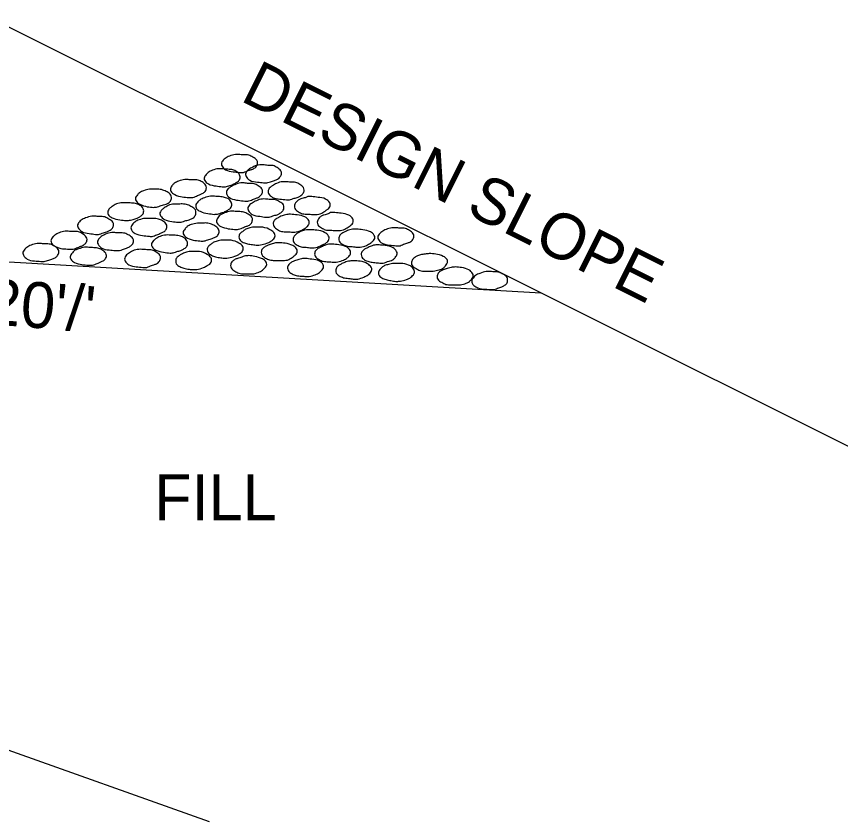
# Model space of a CAD drawing. Extents: x 438659 to 573674, y 10724 to 98600.
# Drawn here: x 516659 to 519895, y 68148 to 71311 of the extents above; entities that cross this region are included whole.
import ezdxf

# ---------------------------------------------------------------- set-up
doc = ezdxf.new("R2010")
doc.units = 0
doc.layers.add('T_Vehicle Path Rt', color=7, linetype='Continuous')

msp = doc.modelspace()

# ---------------------------------------------------------------- linework, layer by layer
at = {"layer": 'T_Vehicle Path Rt'}
for p, q in [((520270.3, 69449), (516544.6, 71311.4)), ((514103.7, 70495.3), (518717.5, 70225)), ((512200.6, 70004), (517415.7, 68148.2))]:
    msp.add_line(p, q, dxfattribs=at)
for points in [[(517534.1, 70698.2), (517509.1, 70701.3), (517480, 70708.9), (517465.7, 70723.7), (517463.5, 70731.4), (517470.8, 70747), (517477.8, 70753.8), (517495, 70762.7), (517518.8, 70768.8), (517531.4, 70768.8), (517550.4, 70767.8), (517571, 70766.4), (517586.8, 70758.4), (517602.5, 70746.2), (517605, 70735.3), (517600.6, 70722.7), (517588.9, 70713), (517577.5, 70708.6), (517560.5, 70702.6), (517550.4, 70698.7), (517534.1, 70698.2)], [(517466.9, 70642.4), (517442.1, 70645.3), (517412, 70653.3), (517397.7, 70667.1), (517395.8, 70675.9), (517403.3, 70690.4), (517411.3, 70697.7), (517428.1, 70707.2), (517451.6, 70713), (517464.5, 70713), (517482.9, 70711), (517504.3, 70709.8), (517519.8, 70703.8), (517534.1, 70689.7), (517536.5, 70681.2), (517532.2, 70666.6), (517521, 70658.4), (517509.8, 70652.3), (517492.6, 70645.8), (517482.9, 70642.9), (517466.9, 70642.4)], [(517629.2, 70657.7), (517605, 70660.8), (517574.6, 70667.9), (517560.1, 70682.7), (517557.9, 70690.2), (517565.6, 70706.2), (517574.1, 70712.3), (517590.6, 70721.7), (517614.2, 70728.3), (517626.3, 70728.3), (517645.7, 70726.3), (517666.3, 70725.4), (517682.6, 70717.4), (517696.9, 70705), (517699.6, 70694.5), (517694.7, 70682.4), (517684.1, 70672), (517671.9, 70667.1), (517655.7, 70661.5), (517645.7, 70658.4), (517629.2, 70657.7)], [(517335.4, 70599.9), (517309.6, 70602.6), (517280, 70611.3), (517264.8, 70624.7), (517263.3, 70634.1), (517270.8, 70648.9), (517279.1, 70656.2), (517295.3, 70664.7), (517319.6, 70670.3), (517332.2, 70670.3), (517351.1, 70669.3), (517372.2, 70668.1), (517387.3, 70661.3), (517401.9, 70647.7), (517404.3, 70638.7), (517399.4, 70624.2), (517388, 70615.7), (517377.1, 70611.1), (517361.1, 70604), (517351.1, 70600.2), (517335.4, 70599.9)], [(517555.5, 70586.3), (517529.5, 70589), (517500.1, 70596.8), (517484.8, 70611.3), (517482.9, 70619.3), (517490.4, 70635.1), (517498.9, 70641.4), (517515.7, 70650.4), (517539.7, 70657.2), (517552.3, 70657.2), (517571, 70655.2), (517591.8, 70654.3), (517607.1, 70645.8), (517622.2, 70634.1), (517624.6, 70623.2), (517619.8, 70610.6), (517608.1, 70600.4), (517597.4, 70596.5), (517581.2, 70590.2), (517571, 70586.6), (517555.5, 70586.3)], [(517719.5, 70591.4), (517693, 70594.1), (517664.4, 70600.6), (517648.4, 70616.2), (517646.7, 70623.7), (517654.5, 70639.5), (517663.2, 70645.8), (517679.9, 70655.7), (517704, 70661.8), (517715.8, 70661.8), (517735, 70660.8), (517755.6, 70659.4), (517771.7, 70651.1), (517785.5, 70639), (517788.2, 70628.8), (517783.5, 70615.4), (517772.6, 70605.7), (517761.2, 70600.4), (517745, 70595.5), (517735, 70591.9), (517719.5, 70591.4)], [(517197.1, 70561.3), (517172.3, 70564), (517142.5, 70574.2), (517128.1, 70586.6), (517125.5, 70595.5), (517133.5, 70610.6), (517141.7, 70618.4), (517157.5, 70626.8), (517181, 70632.4), (517194.4, 70632.4), (517212.8, 70633.4), (517233.5, 70629.3), (517250.2, 70621.8), (517264.8, 70609.4), (517266.9, 70599.9), (517263.3, 70585.8), (517251.4, 70576.1), (517240.7, 70572.5), (517222.8, 70566.7), (517212.8, 70563), (517197.1, 70561.3)], [(517435.3, 70533.9), (517409.9, 70537.1), (517379.8, 70545.8), (517364, 70558.9), (517362.3, 70568.1), (517370.6, 70582.7), (517378.6, 70590.2), (517396.8, 70599.4), (517420.1, 70605), (517431.9, 70605), (517450.9, 70604), (517471.3, 70601.6), (517488, 70595.8), (517501.6, 70581.5), (517504.3, 70573.5), (517499.4, 70558.4), (517488.5, 70550.7), (517477.3, 70544.6), (517461.8, 70539.3), (517451.6, 70535.9), (517435.3, 70533.9)], [(517639.2, 70522.5), (517613.9, 70526.1), (517584.3, 70533.2), (517569.8, 70548), (517567.3, 70555.8), (517574.9, 70572), (517583.6, 70577.6), (517600.6, 70587.5), (517624.1, 70594.1), (517636.5, 70594.1), (517654.9, 70592.1), (517676.1, 70590.9), (517691.6, 70583.2), (517706.9, 70570.8), (517709.1, 70560.4), (517704.7, 70547.7), (517692.8, 70538), (517682.1, 70532.5), (517665.1, 70527.6), (517654.9, 70523.5), (517639.2, 70522.5)], [(517818.2, 70604), (517842.8, 70600.6), (517872.6, 70594.1), (517888.6, 70579), (517890.6, 70571.8), (517883.5, 70555.5), (517874.5, 70549.7), (517857.1, 70538.8), (517833.5, 70533.2), (517821.2, 70533.2), (517803, 70534.9), (517781.4, 70536.3), (517765.6, 70543.6), (517751.8, 70556.5), (517749.8, 70566.7), (517754.4, 70579.5), (517764.4, 70589.5), (517775.5, 70595.1), (517792, 70599.4), (517802.5, 70603.6), (517818.2, 70604)], [(517089.8, 70509.4), (517064.1, 70512.1), (517034.7, 70520.1), (517018.9, 70533.4), (517017.2, 70542.4), (517024.3, 70557.2), (517034, 70564.5), (517051.2, 70574.9), (517074.8, 70579.5), (517086.6, 70579.5), (517105.1, 70578.6), (517126.2, 70576.4), (517142, 70570.3), (517156.5, 70556), (517158.2, 70547.7), (517153.6, 70533.2), (517142.5, 70524.7), (517132, 70518.9), (517116.2, 70513.8), (517106.1, 70511.1), (517089.8, 70509.4)], [(517293.6, 70502.9), (517268.6, 70505.8), (517239.8, 70513.8), (517224.5, 70528.1), (517221.8, 70535.4), (517229.8, 70552.1), (517238.8, 70558.9), (517253.8, 70568.6), (517278.1, 70574.2), (517291, 70574.2), (517309.6, 70574.7), (517330.8, 70571.3), (517346.8, 70563), (517361.6, 70551.1), (517363.5, 70541.4), (517359.4, 70527.6), (517348.2, 70517.4), (517336.6, 70512.6), (517319.6, 70507.9), (517309.6, 70504.6), (517293.6, 70502.9)], [(516969.2, 70455.3), (516944, 70458.2), (516915.1, 70466.2), (516901, 70480.8), (516898.3, 70488.8), (516905.6, 70504.6), (516912.7, 70511.1), (516929.6, 70519.6), (516953.9, 70526.6), (516966.3, 70526.6), (516984.7, 70525.2), (517005.8, 70523.5), (517021.6, 70515.5), (517037.4, 70503.3), (517039.6, 70492.9), (517035.2, 70479.8), (517023.3, 70470.3), (517012.9, 70465.7), (516995.4, 70459.4), (516984.7, 70455.8), (516969.2, 70455.3)], [(517179.6, 70447.5), (517153.6, 70450.7), (517124.7, 70458.4), (517110.2, 70472.5), (517108.2, 70481.3), (517115.8, 70496.3), (517122.8, 70503.8), (517140.3, 70512.3), (517163.8, 70517.9), (517176.2, 70517.9), (517195.4, 70517.2), (517216.2, 70515.5), (517231.8, 70508.7), (517247, 70495.1), (517249.2, 70486.4), (517244.4, 70471.6), (517233.5, 70463.5), (517221.8, 70458.2), (517205.1, 70451.7), (517195.4, 70447.8), (517179.6, 70447.5)], [(517514.9, 70474.9), (517490.2, 70477.6), (517460.8, 70486.4), (517446, 70499.9), (517444.3, 70508.7), (517451.6, 70524), (517458.6, 70530.8), (517476.1, 70539.3), (517499.6, 70545.8), (517512, 70545.8), (517530.9, 70544.6), (517551.8, 70542.9), (517567.8, 70534.9), (517583.4, 70522.5), (517585.1, 70512.6), (517580.9, 70499), (517569.8, 70490), (517558.4, 70485.9), (517541.4, 70478.8), (517530.9, 70475.4), (517514.9, 70474.9)], [(517735.3, 70534.4), (517761.2, 70531.7), (517790.8, 70524), (517806.4, 70509.6), (517808.1, 70501.2), (517800.8, 70486.6), (517792, 70479.3), (517774.6, 70469.9), (517751.3, 70464.3), (517738.4, 70464.3), (517720.2, 70465.7), (517699.1, 70466.7), (517683.6, 70473.7), (517669, 70487.3), (517666.8, 70496.3), (517671.2, 70510.1), (517683.1, 70518.9), (517693, 70524.7), (517710, 70530.8), (517720.2, 70533.4), (517735.3, 70534.4)], [(517908.5, 70540.9), (517934, 70538.3), (517963.6, 70530.8), (517979.4, 70516), (517981.3, 70508.4), (517973.5, 70492.4), (517965.3, 70486.4), (517947.6, 70475.7), (517924.8, 70470.3), (517911.7, 70470.3), (517892.7, 70471.6), (517871.1, 70473), (517856.3, 70481), (517841.8, 70493.1), (517839.8, 70503.8), (517844.7, 70516.7), (517855.1, 70526.6), (517866, 70531), (517883, 70536.3), (517892.3, 70540.5), (517908.5, 70540.9)], [(517384.4, 70428.8), (517359.4, 70431.5), (517330.3, 70440.5), (517315.2, 70453.6), (517312.8, 70462.1), (517320.6, 70477.1), (517329.3, 70485.9), (517344.6, 70493.6), (517368.9, 70499), (517381.2, 70499), (517399.7, 70499.9), (517420.8, 70496.3), (517437, 70489), (517452.1, 70475.7), (517454.3, 70467.4), (517449.9, 70452.6), (517438.5, 70444.1), (517427.1, 70438.8), (517410.3, 70433.9), (517399.7, 70430.1), (517384.4, 70428.8)], [(517602, 70483.7), (517626.3, 70483), (517657.4, 70472), (517671.4, 70458.4), (517673.9, 70449.7), (517665.9, 70434.9), (517657.9, 70427.9), (517641.4, 70420.4), (517616.8, 70413.8), (517604.5, 70412.8), (517585.5, 70414.8), (517565.6, 70417.9), (517549.4, 70423.3), (517534.6, 70435.9), (517532.4, 70444.9), (517536.8, 70458.9), (517548.7, 70467.9), (517559.1, 70475.4), (517575.3, 70480.8), (517585.8, 70483), (517602, 70483.7)], [(516864.9, 70397.3), (516839.4, 70399), (516811.2, 70407.5), (516795.7, 70421.3), (516793.8, 70430.1), (516801.5, 70445.3), (516809.5, 70452.4), (516826, 70461.6), (516849.3, 70467.4), (516861.9, 70467.4), (516881.6, 70466.5), (516902.7, 70465.2), (516917.5, 70457.5), (516932.8, 70444.6), (516935.5, 70434.9), (516930.6, 70421.1), (516919.9, 70412.3), (516907.6, 70407), (516890.6, 70400.2), (516881.6, 70397.3), (516864.9, 70397.3)], [(517047.6, 70391.7), (517022.1, 70394.1), (516993.7, 70401.4), (516978.9, 70416.2), (516976.5, 70424.2), (516984.2, 70440), (516991.5, 70446.3), (517008.5, 70455.8), (517032.8, 70462.1), (517044.2, 70462.1), (517063.6, 70460.9), (517084.2, 70459.4), (517100.5, 70451.7), (517115.8, 70438.8), (517118.2, 70429.1), (517113.3, 70415.5), (517101.9, 70406.3), (517090.8, 70400.9), (517074.5, 70395.6), (517063.6, 70392), (517047.6, 70391.7)], [(517262.3, 70381.5), (517236.4, 70384.7), (517206.3, 70393.4), (517191, 70406.5), (517188.3, 70415.5), (517196.6, 70430.5), (517205.1, 70437.6), (517222.3, 70447), (517245.8, 70452.6), (517258.4, 70452.6), (517276.9, 70451.9), (517298, 70449.7), (517314, 70443.2), (517328.1, 70429.3), (517330.8, 70420.4), (517325.7, 70406.3), (517314.3, 70397.3), (517303.6, 70392.2), (517287.8, 70387.4), (517277.6, 70383.5), (517262.3, 70381.5)], [(517812.9, 70473.5), (517838.4, 70471.6), (517868.5, 70463.1), (517884.5, 70448.3), (517886.4, 70440), (517878.2, 70424.5), (517869.4, 70418.4), (517852, 70410.4), (517828, 70402.2), (517815.3, 70402.2), (517796.6, 70404.3), (517776.3, 70406.5), (517761, 70413.3), (517746.9, 70425.7), (517744.5, 70435.4), (517749.3, 70448.7), (517759.3, 70458.2), (517769.7, 70464.3), (517786.2, 70470.3), (517796.9, 70472.5), (517812.9, 70473.5)], [(517993.9, 70475.7), (518018.9, 70473), (518048.3, 70465.5), (518063.8, 70451.4), (518066, 70443.2), (518057.3, 70427.4), (518049, 70421.1), (518032.5, 70411.9), (518008.5, 70405.1), (517996.1, 70405.1), (517977.4, 70407), (517956.8, 70408.5), (517940.8, 70415.5), (517926.2, 70428.8), (517924.8, 70438.1), (517928.2, 70451.7), (517939.8, 70460.9), (517950.5, 70466.2), (517967.2, 70473), (517978.4, 70475.4), (517993.9, 70475.7)], [(518148.7, 70410.4), (518123.7, 70413.3), (518094.4, 70421.1), (518079.8, 70435.2), (518077.4, 70443.6), (518085.6, 70458.9), (518092.9, 70465.7), (518109.9, 70474.5), (518133, 70481), (518146.3, 70481), (518165, 70479.8), (518185.9, 70478.1), (518201.4, 70470.3), (518216.7, 70457.7), (518218.9, 70447.5), (518214.5, 70434.4), (518203.6, 70425), (518191.9, 70420.8), (518174.5, 70414.3), (518165, 70410.6), (518148.7, 70410.4)], [(516754.2, 70348.8), (516729.2, 70351), (516700.3, 70358.2), (516686, 70373.3), (516683.4, 70381), (516691.6, 70397.3), (516698.6, 70403.6), (516715.6, 70413.3), (516739.7, 70419.1), (516751.5, 70419.1), (516771, 70417.9), (516792.1, 70416.2), (516808.3, 70408.7), (516822.4, 70396.3), (516825.1, 70386.1), (516820.2, 70372.8), (516810, 70363.3), (516797.2, 70357.7), (516780.9, 70352.4), (516771, 70349.3), (516754.2, 70348.8)], [(517477.1, 70432.5), (517502.1, 70431.8), (517532.2, 70421.3), (517547, 70407.5), (517549.1, 70398.5), (517541.4, 70383.5), (517532.4, 70376.7), (517516.1, 70369.2), (517491.1, 70362.4), (517479.3, 70361.1), (517460.8, 70363.3), (517440.7, 70367), (517424.4, 70373.3), (517409.9, 70384.7), (517407.7, 70394.6), (517412, 70408), (517423.4, 70417), (517433.9, 70424.2), (517450.9, 70429.3), (517461.3, 70431.8), (517477.1, 70432.5)], [(517688.4, 70422.3), (517713.4, 70420.4), (517743.5, 70411.4), (517758.8, 70397.8), (517761.2, 70389.8), (517753.5, 70374.2), (517745, 70367.5), (517727.7, 70356.3), (517704.7, 70352.4), (517691.6, 70352.4), (517672.4, 70352.9), (517652, 70354.8), (517636.5, 70362.1), (517622.2, 70375.5), (517619.8, 70384.7), (517624.6, 70398.3), (517635.8, 70407.5), (517646.7, 70412.8), (517662.7, 70417.9), (517672.2, 70421.1), (517688.4, 70422.3)], [(516941.5, 70334), (516915.6, 70336.4), (516886.2, 70344.6), (516871.7, 70358.2), (516869.2, 70367.5), (516878.2, 70382.5), (516884.3, 70389.8), (516902.7, 70398.3), (516925.8, 70404.3), (516937.9, 70404.3), (516957.1, 70403.1), (516977.7, 70401.4), (516993.7, 70394.6), (517009, 70381), (517011.7, 70372.1), (517006.3, 70357.5), (516995.4, 70349.5), (516984.2, 70344.2), (516966.8, 70337.4), (516957.1, 70334.5), (516941.5, 70334)], [(517154.1, 70325.2), (517128.9, 70328.1), (517100, 70335.9), (517085.2, 70350.5), (517083.2, 70357.7), (517090.8, 70374.2), (517098.3, 70380.3), (517115, 70390.3), (517138.8, 70396.3), (517151.2, 70396.3), (517170.6, 70395.1), (517191, 70393.4), (517206.8, 70385.7), (517221.8, 70373.3), (517224.5, 70362.8), (517220.3, 70349.7), (517208.5, 70339.8), (517197.5, 70335.7), (517180.1, 70329.6), (517170.6, 70325.5), (517154.1, 70325.2)], [(517353.3, 70387.8), (517377.3, 70387.4), (517407.7, 70376.7), (517422.5, 70362.8), (517424.9, 70354.6), (517417.4, 70338.6), (517407.9, 70332.8), (517392.4, 70324.5), (517367.4, 70317.7), (517355, 70316.7), (517336.6, 70318.2), (517316.2, 70322.3), (517300.4, 70328.6), (517285.9, 70339.8), (517283.7, 70350.2), (517287.8, 70363.3), (517299.2, 70372.8), (517309.9, 70379.3), (517326.4, 70384.7), (517337.1, 70387.4), (517353.3, 70387.8)], [(517899, 70416.5), (517924.8, 70414.3), (517954.1, 70405.8), (517968.7, 70392), (517970.9, 70383.2), (517963.6, 70368.4), (517954.6, 70360.7), (517938.1, 70352.4), (517914.3, 70346.1), (517902.4, 70346.1), (517883.5, 70347.8), (517862.7, 70349.3), (517846.9, 70356.3), (517831.1, 70369.2), (517829.4, 70377.9), (517834, 70392.4), (517845.9, 70400.9), (517856.6, 70406.3), (517872.6, 70413.3), (517883.5, 70416.2), (517899, 70416.5)], [(518082.3, 70413.6), (518106.8, 70411.9), (518137.6, 70402.2), (518151.4, 70388.3), (518153.6, 70379.3), (518146.3, 70364.3), (518139, 70357), (518121.6, 70350.2), (518098, 70342.5), (518085.6, 70342.5), (518066, 70344.2), (518046.1, 70347.3), (518029.8, 70353.1), (518015, 70365.8), (518012.1, 70375.9), (518017.5, 70389.3), (518028.1, 70398.3), (518040.3, 70404.1), (518055.8, 70410.6), (518066, 70413.3), (518082.3, 70413.6)], [(517569.8, 70371.8), (517594.5, 70368.9), (517624.1, 70358.7), (517638.9, 70346.3), (517641.4, 70337.4), (517633.1, 70322.8), (517624.6, 70314.8), (517608.1, 70305.6), (517584.3, 70300), (517572, 70300), (517553.3, 70299.8), (517532.4, 70302.9), (517516.1, 70310.7), (517501.6, 70323.5), (517499.4, 70332.3), (517504.3, 70346.8), (517514.9, 70355.8), (517526.6, 70360.7), (517543.6, 70366.2), (517553.3, 70369.6), (517569.8, 70371.8)], [(517793.3, 70360.7), (517818.7, 70357.5), (517848.1, 70350.5), (517862.7, 70335.9), (517864.8, 70327.7), (517856.6, 70312.6), (517849.1, 70305.6), (517831.6, 70296.8), (517808.1, 70290), (517796.2, 70290), (517777.7, 70291.3), (517756.6, 70293.4), (517740.6, 70300), (517725.3, 70313.6), (517723.1, 70322.8), (517727.7, 70336.4), (517738.9, 70345.9), (517750.5, 70351), (517767.3, 70356.3), (517777.7, 70359.7), (517793.3, 70360.7)], [(518279.8, 70379.8), (518304.8, 70377.9), (518334.4, 70368.9), (518349.4, 70356.3), (518351.4, 70348.8), (518343.6, 70332), (518336.1, 70323.5), (518318.1, 70316), (518295.1, 70310.9), (518282.9, 70310.2), (518264, 70310.2), (518242.4, 70313.6), (518227.8, 70320.9), (518212.3, 70332.8), (518209.9, 70342.5), (518214.3, 70356.3), (518225.9, 70366.7), (518236.8, 70371.8), (518253.8, 70376.7), (518263.8, 70377.9), (518279.8, 70379.8)], [(517982.8, 70351), (518008.5, 70349.5), (518037.4, 70339.5), (518051.7, 70325.7), (518054.1, 70316.7), (518046.3, 70301.9), (518039.3, 70295.6), (518022.3, 70287.6), (517998.5, 70279.1), (517985.9, 70279.1), (517967.2, 70281.6), (517947.1, 70284), (517930.1, 70290), (517914.6, 70302.9), (517912.2, 70312.9), (517917.2, 70326.2), (517928.2, 70335.7), (517939.8, 70341.5), (517956.8, 70348.3), (517967.2, 70350.5), (517982.8, 70351)], [(518150.9, 70341), (518175.4, 70340.3), (518205.5, 70331.1), (518219.1, 70317.2), (518221.8, 70309.7), (518214.3, 70293), (518206.7, 70286.4), (518190.2, 70277.4), (518166, 70271.8), (518152.4, 70270.4), (518134.4, 70272.8), (518114, 70276.5), (518097.5, 70281.6), (518082.7, 70294.2), (518080.1, 70302.9), (518085.4, 70316.7), (518095.8, 70327.2), (518107.2, 70333.7), (518124.5, 70337.6), (518134.9, 70340.3), (518150.9, 70341)], [(518381.4, 70327.2), (518406.7, 70324.5), (518435.6, 70315.5), (518449.6, 70301.9), (518452.3, 70294.2), (518445.3, 70277.7), (518437.3, 70270.4), (518419.8, 70261.4), (518396, 70256.6), (518383.9, 70256.6), (518364.9, 70257), (518344.8, 70258.7), (518328.5, 70266.8), (518313, 70278.6), (518310.6, 70289.3), (518315, 70302.4), (518326.8, 70312.4), (518337.5, 70316.7), (518354.8, 70322.3), (518365.7, 70325.5), (518381.4, 70327.2)], [(518518.1, 70238.4), (518492.1, 70240.5), (518463, 70248.6), (518448.4, 70262.9), (518446.5, 70271.4), (518454.7, 70287.4), (518461.3, 70293.7), (518478.7, 70301.9), (518502.8, 70309.5), (518515.1, 70309.5), (518533.6, 70308), (518554.5, 70306.1), (518570.2, 70298.3), (518585.5, 70285.9), (518587.2, 70276.5), (518583.6, 70261.9), (518572.4, 70253.4), (518561.2, 70248.1), (518543.8, 70241.8), (518533.6, 70238.6), (518518.1, 70238.4)]]:
    msp.add_spline(points, degree=3, dxfattribs=at)

# ---------------------------------------------------------------- texts
for s, rotation, p in [('DESIGN SLOPE', 333.435, (517532.8, 70982.5)), ("0.020'/'", 355.6232, (516203.1, 70128.5))]:
    msp.add_text(s, height=180, rotation=rotation, dxfattribs=at).set_placement(p)
msp.add_text('FILL', height=180, dxfattribs=at).set_placement((517199.3, 69332))

doc.saveas('drawing.dxf')
